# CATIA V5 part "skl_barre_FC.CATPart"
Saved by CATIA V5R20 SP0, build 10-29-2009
Part number: skl_barre_FC
Publications: "Axe_pivot_FC_C", "Axe_pivot_FC_F", "Droite_FC"
Bounding box of the stored display mesh (mm): x 5 to 10, y -5.995 to 30.995, z -5.992 to 155.992
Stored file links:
  D:\Dropbox\IAO_2012\IAO_2012_742_prousseau\skl_barre_FC.CATPart
  D:\Dropbox\IAO_2012\IAO_2012_742_prousseau\skl_IAO.CATProduct
  D:\Dropbox\IAO_2012\IAO_2012_742_prousseau\skl_barre_BC.CATPart
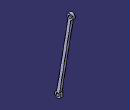
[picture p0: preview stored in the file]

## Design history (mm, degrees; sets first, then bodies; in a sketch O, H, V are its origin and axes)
Set1
  Point1 "Point_F": linked copy from another document
  Point2 "Point_C": linked copy from another document
Set2
  Line1 "Droite_FC": type PtPt, FirstPoint Point3, SecondPoint Point4
  Point3 "Point_F": stored without definition
  Point4 "Point_C": stored without definition
  Line2 "Axe_pivot_FC_F": type Normal, RefPoint Point3, RefSkin Plane1, Start -20, End 20
  Plane1 "Plan_Ref": stored without definition
  Line3 "Axe_pivot_FC_C": type Normal, RefPoint Point4, RefSkin Plane2, Start -20, End 20
  Plane2 "Plan_Ref": stored without definition
  Plane3: type Offset, RefPlane yz-plane, Offset 5
Body1 (main body)
  Sketch1 on Plane3, origin (5, 0, 0), H (0, 1, 0), V (0, 0, 1)
    line L1 (21.1866, 145.3677) -> (-2.1049, 5.6187)
    line L2 (3.8134, 4.6323) -> (27.1049, 144.3813)
    reference projected line E1 (0, 0) -> (25, 150) from Line1
    reference projected line E2 (0, 0) -> (25, 150) from Line1
    circle A1 centre (0, 0) radius 3
    point P1 (0, 0)
    reference projected point E3 (0, 0) from Point1
    arc A2 centre (0, 0) radius 6 from (-2.1049, 5.6187) to (3.8134, 4.6323) ccw
    point P2 (0, 0)
    reference projected point E4 (0, 0) from Point1
    arc A3 centre (25, 150) radius 6 from (27.1049, 144.3813) to (21.1866, 145.3677) ccw
    point P5 (25, 150)
    circle A4 centre (25, 150) radius 3
    point P6 (25, 150)
    reference projected point E5 (25, 150) from Point2
    reference projected point E6 (25, 150) from Point2
    distance L2 L1 = 6
    radius A1 = 3
    radius A2 = 6
    radius A4 = 3
    radius A3 = 6
    parallelism: L1 E1
    symmetry: L1 L2 E2
    coincidence: P1 E3, P2 E4, P6 E5, P5 E6
  Pad1: profile Sketch1, direction (1, 0, 0), length 5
